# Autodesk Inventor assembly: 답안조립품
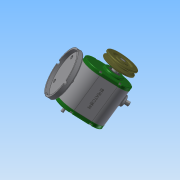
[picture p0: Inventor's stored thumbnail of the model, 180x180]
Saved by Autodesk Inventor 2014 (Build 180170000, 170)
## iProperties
Created: 2017-09
Part Number: 답안조립품
Document SubType Name: Assembly
Designer: user
Author: user
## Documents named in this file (17)
- C:\Users\user\Desktop\370907V1015\답안조립품.iam
- C:\Users\user\Desktop\370907V1015\본체.ipt
- C:\Users\user\Desktop\370907V1015\V-벨트풀리.ipt
- C:\Users\user\Desktop\370907V1015\뒤커버.ipt
- C:\Users\user\Desktop\370907V1015\멈춤나사 M3x10.ipt
- C:\Users\user\Desktop\370907V1015\메인축.ipt
- C:\Users\user\Desktop\370907V1015\베어링 608.ipt
- C:\Users\user\Desktop\370907V1015\베어링 6003.ipt
- C:\Users\user\Desktop\370907V1015\볼트 M4.ipt
- C:\Users\user\Desktop\370907V1015\부시.ipt
- C:\Users\user\Desktop\370907V1015\서브축.ipt
- C:\Users\user\Desktop\370907V1015\슬라이더.ipt
- C:\Users\user\Desktop\370907V1015\앞커버.ipt
- C:\Users\user\Desktop\370907V1015\오일실 8 22 7.ipt
- C:\Users\user\Desktop\370907V1015\오일실 17 32 8.ipt
- C:\Users\user\Desktop\370907V1015\키 5 x 5 x 18.ipt
- C:\Users\user\Desktop\370907V1015\가변스프링.ipt
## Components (2 placed, 2 different names)
1. V-벨트풀리:1 — 플러쉬:1
2. 가변스프링:1
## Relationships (1: Flush 1)
- 플러쉬:1 [Flush]: V-벨트풀리:1
